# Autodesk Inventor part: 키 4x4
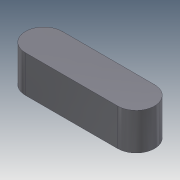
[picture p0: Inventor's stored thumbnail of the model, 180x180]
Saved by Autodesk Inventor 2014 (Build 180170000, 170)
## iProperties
Company: 한국ATC센터
Created: 2014-10
Part Number: 키 4x4
Document SubType Name: Modeling
Designer: KYOUNG IL JANG
Density: 7.85 g/cm^3
Mass: 1.65058 g
Surface Area: 2.35398 cm^2
Volume: 0.210265 cm^3
Material: 강철
Appearance: 강철 - 광택
Author: KYOUNG IL JANG
Revision Number: 1
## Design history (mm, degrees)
sketch "스케치1"
  geometry: L1 (-5, -2)-(5, -2); L2 (5, 2)-(-5, 2); A1 r 2 centre (5, 0) between (5, -2) and (5, 2); A2 r 2 centre (-5, 0) between (-5, 2) and (-5, -2); 2 further points
  constraints: 4 end point, 4 point on circle, 4 tangent, 2 centre point, 1 horizontal, 1 horizontal alignment, 1 midpoint, 1 parallel, 1 vertical alignment
  dimensions: "d0" = 4 distance between parallel lines of L1 L2; "d1" = 14 dimension on A1 A2
extrude "돌출1" new body sketch "스케치1" stored distance "d2" = 4; taper "d3" = 0 deg
node "솔리드1"
